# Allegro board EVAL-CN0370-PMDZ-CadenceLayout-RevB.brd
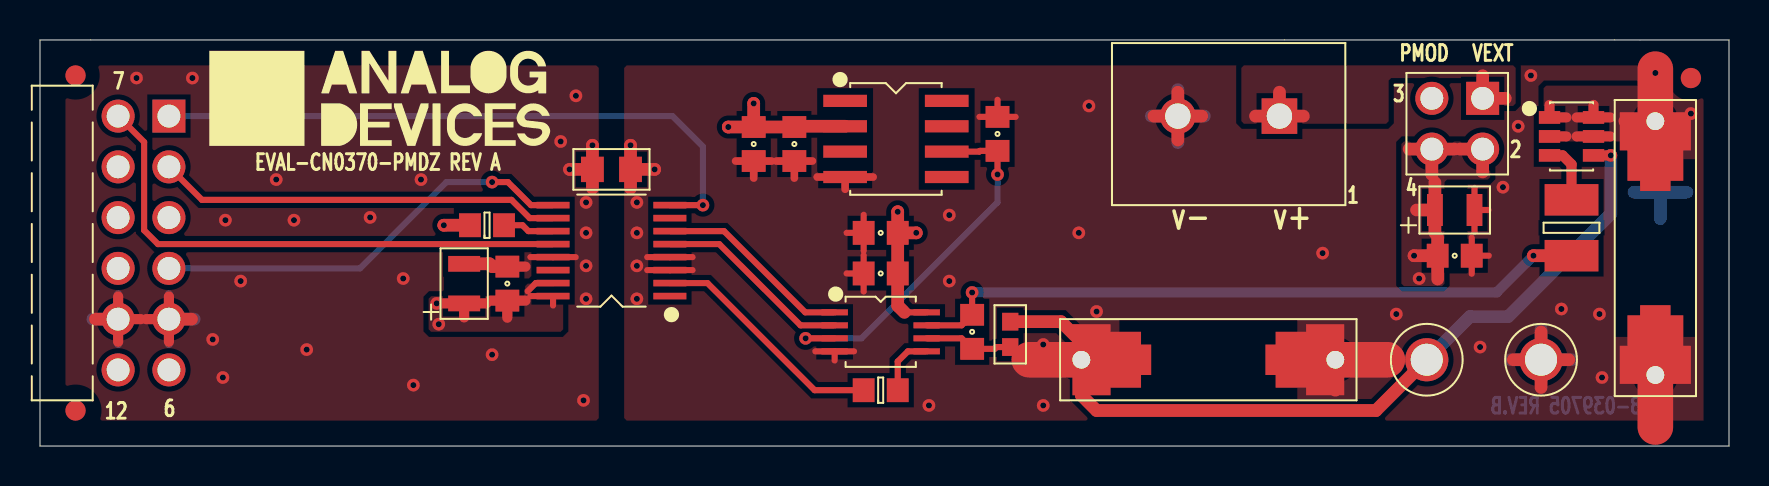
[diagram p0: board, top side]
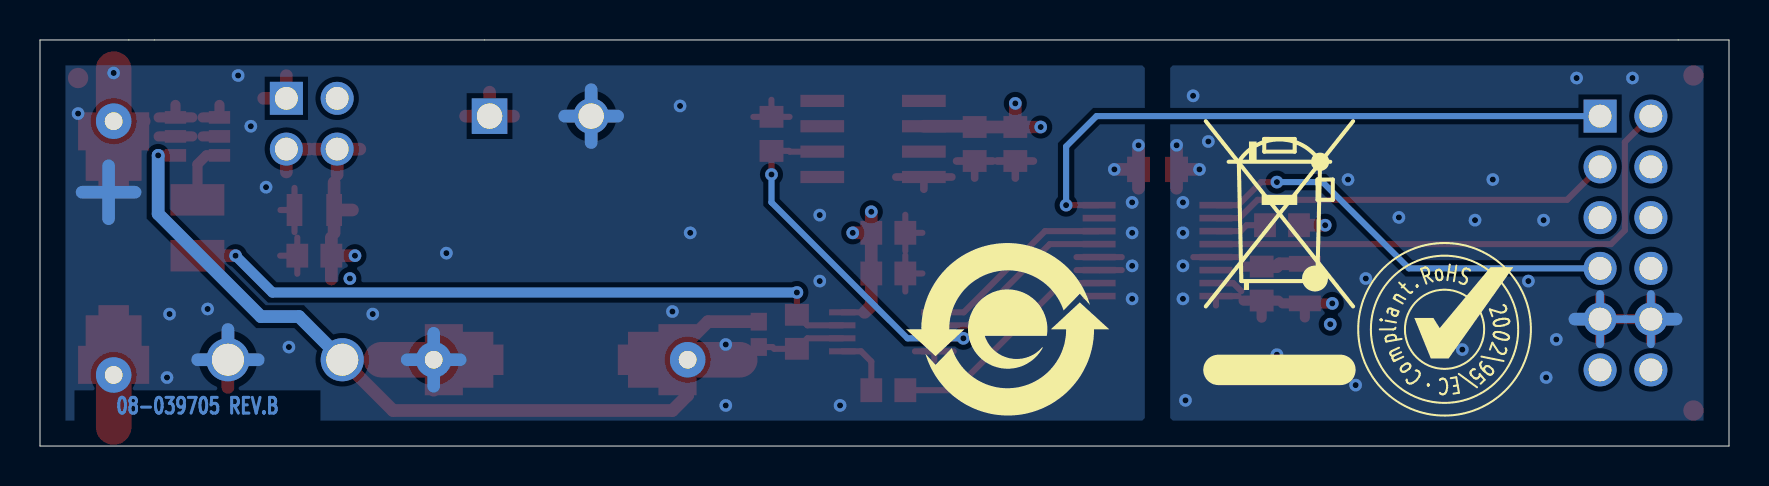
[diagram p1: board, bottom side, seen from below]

Outline 84.45 x 20.32 mm; copper layers: TOP, L2_GND, L3_PWR, BOTTOM. Coordinates in mm from the lower left corner of the outline.
Outline path: 0,20.32 0,0 84.45,0 84.45,20.32 0,20.32

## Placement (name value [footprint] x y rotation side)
A1  ADA4500-2ARMZ  [MSOP8]  42.04 5.71 270 top
AGND  BLK  [CNLOOPTP]  75.06 4.32 0 top
C1  10UF  [C0603]  35.69 15.11 270 top
C2  0.1uF  [C0603]  37.72 15.11 270 top
C4  0.1uF  [C0603]  47.88 15.62 90 top
C5  10UF  [C0603]  42.04 10.67 180 top
C6  0.1uF  [C0603]  42.04 8.64 180 top
C7  10uF  [CPL0805]  21.21 8.13 90 top
C8  0.1uF  [C0603]  23.37 8.13 90 top
C13  22PF  [C0603]  46.61 5.71 270 top
C14  10uF  [CPL0805]  70.74 11.81 0 top
C15  0.1uF  [C0603]  70.74 9.52 0 top
E2  330OHM  [L0805]  28.58 13.84 180 top
LED  TBD_SPACER_500_D37  [R_SPACER_500_D37]  80.77 16.26 270 top
LED_SUPPLY  TSW-102-08-G-D  [CNSAMTEC2X2H338LD36]  72.14 17.4 180 top
NOREF  -  []  1.91 18.41 0 top
NOREF#2  -  [unnamed#2]  82.55 18.41 0 top
NOREF#3  -  []  0 20.32 0 top
NOREF#4  -  []  -149.1 -230.5 0 top
NOREF#5  -  []  1.91 18.41 0 top
NOREF#6  -  []  -157.99 -240.92 0 top
NOREF#7  -  []  84.45 20.32 180 top
NOREF#8  -  []  0 -20.32 0 top
NOREF#9  -  []  0 0 0 top
NOREF#10  -  []  83.51 0 90 top
NOREF#11  -  []  17.02 17.4 0 top
NOREF#12  -  []  -13.97 231.78 0 top
NOREF#13  -  []  0 20.32 0 top
NOREF#14  -  []  0 1.54 0 top
NOREF#15  -  []  84.45 -20.32 90 top
NOREF#16  -  []  0 20.32 270 top
NOREF#17  -  []  84.45 20.32 0 top
NOREF#18  -  []  208.41 236.85 0 top
NOREF#19  -  [unnamed#2]  1.78 1.78 0 top
NOREF#20  -  []  36.83 36.83 0 top
NOREF#21  -  [unnamed#2]  1.78 18.54 0 top
NOREF#22  -  []  -156.72 -239.65 0 top
NOREF#23  -  []  36.07 5.84 180 bottom
NOREF#24  -  []  13.21 19.94 180 bottom
NOREF#25  -  []  14.22 5.84 180 bottom
PMOD  TSW-106-25-F-D-RA  [CNHDRRA2X6H240]  6.45 16.51 270 top
Q1  IRLMS2002TRPBF  [SOT23_6-3]  76.58 15.49 270 top
R1  10K  [R0603]  22.35 11.05 0 top
R2  0  [R0603]  42.04 2.79 0 top
R4  22  [R1210]  76.58 10.92 90 top
R5  6.2K  [R0402]  48.51 5.59 90 top
R_LIMIT  TBD_SPACER_500_D37  [R_SPACER_500_D37]  64.77 4.32 180 top
U1  AD5542ABRUZ  [TSSOP16]  28.58 9.78 90 top
U2  ADR4525BRZ  [SO8]  42.8 15.37 270 top
VEXT  OSTTC022162  [CNHDR1X2H406]  61.98 16.51 180 top
VOUT  BLK  [CNLOOPTP]  69.34 4.32 270 top

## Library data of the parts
A1 = ADA4500_2: User Part Number: UPN; part number: ADA4500_2_SM-ADA4500-2ARMZ,E017613,MSOP8
AGND VOUT = CNTP1P: User Part Number: UPN; alternate symbols: (CNBANANA_ALT); part number: CNTP1P_TH-BLK,E000948,CNLOOPTP
C1 C5 = CAP: Tolerance: 20; User Part Number: UPN; part number: CAP_SM-10UF,6.3V,20,E007143,C0603; tolerance: 20
C2 C4 C6 C8 C15 = CAP: Tolerance: 5; User Part Number: UPN; part number: CAP_SM-0.1UF,16V,5,E022221,C0603; tolerance: 5
C7 C14 = CAPP: Tolerance: 20; User Part Number: UPN; part number: CAPP_SM-10UF,6.3V,20,E020901,CPL0805; tolerance: 20
C13 = CAP: Tolerance: 5; User Part Number: UPN; part number: CAP_SM-22PF,50V,5,E000411,C0603; tolerance: 5
E2 = FERRITE: Tolerance: 25; User Part Number: UPN; alternate symbols: (L1210H59_ALT); part number: FERRITE_SM-330OHM,25,E018120,L0805; tolerance: 25
LED R_LIMIT = RES: User Part Number: UPN; part number: RES_TH-TBD_SPACER_500_D37,E018836,TBD_SPACER_500_D37,TBD_SPACER_500_D37,R_SPACER_500_D37
LED_SUPPLY = CN4P: User Part Number: UPN; part number: CN4P_TH-TSW-102-08-G-D,E006588,CNSAMTEC2X2H338LD36
PMOD = CN12P_V3: User Part Number: UPN; part number: CN12P_V3_TH-TSW-106-25-F-D-RA,E018495,CNHDRRA2X6H240
Q1 = TRANNMOSFET_V17: User Part Number: UPN; part number: TRANNMOSFET_V17_SM-IRLMS2002TRPBF,E018862,SOT23_6-3
R1 = RES: Tolerance: 1; User Part Number: UPN; part number: RES_SM-10K,E003671,1/10W,1,R0603; tolerance: 1
R2 = RES: Tolerance: 5; User Part Number: UPN; part number: RES_SM-0,E006826,1/10W,5,R0603; tolerance: 5
R4 = RES: Tolerance: 5; User Part Number: UPN; part number: RES_SM-22,E013618,1/2W,5,R1210; tolerance: 5
R5 = RES: Tolerance: 5; User Part Number: UPN; part number: RES_SM-6.2K,E003460,1/16W,5,R0402; tolerance: 5
U1 = AD5542A: User Part Number: UPN; part number: AD5542A_SM-AD5542ABRUZ,E016103,TSSOP16
U2 = ADR45XX: User Part Number: UPN; part number: ADR45XX_SM-ADR4525BRZ,E016680,SO8
VEXT = CN2P: User Part Number: UPN; part number: CN2P_TH-OSTTC022162,E016936,CNHDR1X2H406

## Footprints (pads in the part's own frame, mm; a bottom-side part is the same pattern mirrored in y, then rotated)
C0603
  rect 1.092x1.194 smd: 1(-0.851,0) 2(0.851,0)
CNHDR1X2H406
  rect 1.778x1.778 hole 1.27: 1(0,0)
  round 1.778 hole 1.27: 2(5.08,0)
CNHDRRA2X6H240
  rect 1.651x1.651 hole 1.143: 1(0,0)
  round 1.651 hole 1.143: 2(2.54,0) 3(5.08,0) 4(7.62,0) 5(10.16,0) 6(12.7,0) 7(0,-2.54) 8(2.54,-2.54) 9(5.08,-2.54) 10(7.62,-2.54) 11(10.16,-2.54) 12(12.7,-2.54)
CNLOOPTP
  round 2.159 hole 1.6: 1(0,0)
CNSAMTEC2X2H338LD36
  rect 1.651x1.651 hole 1.143: 1(0,0)
  round 1.651 hole 1.143: 2(0,2.54) 3(2.54,0) 4(2.54,2.54)
CPL0805
  rect 0.787x1.6 smd: N(0.991,0) P(-0.991,0)
L0805
  rect 1.143x1.27 smd: 1(-0.953,0) 2(0.953,0)
MSOP8
  rect 0.305x1.321 smd: 1(-0.975,-2.301) 2(-0.325,-2.301) 3(0.325,-2.301) 4(0.975,-2.301) 5(0.975,2.301) 6(0.325,2.301) 7(-0.325,2.301) 8(-0.975,2.301)
R0402
  rect 0.889x0.813 smd: 1(-0.635,0) 2(0.635,0)
R0603
  rect 1.092x1.194 smd: 1(-0.851,0) 2(0.851,0)
R1210
  rect 1.575x2.692 smd: 1(-1.397,0) 2(1.397,0)
R_SPACER_500_D37
  custom 0.889x0.889 hole 0.94: 1(0,0) 2(12.7,0)
SO8
  rect 0.61x2.184 smd: 1(-1.905,-2.54) 2(-0.635,-2.54) 3(0.635,-2.54) 4(1.905,-2.54) 5(1.905,2.54) 6(0.635,2.54) 7(-0.635,2.54) 8(-1.905,2.54)
SOT23_6-3
  rect 0.635x1.067 smd: 1(-0.95,-1.1) 2(0,-1.1) 3(0.95,-1.1) 4(0.95,1.1) 5(0,1.1) 6(-0.95,1.1)
TSSOP16
  rect 0.33x1.651 smd: 1(-2.276,-2.921) 2(-1.626,-2.921) 3(-0.975,-2.921) 4(-0.325,-2.921) 5(0.325,-2.921) 6(0.975,-2.921) 7(1.626,-2.921) 8(2.276,-2.921) 9(2.276,2.921) 10(1.626,2.921) 11(0.975,2.921) 12(0.325,2.921) 13(-0.325,2.921) 14(-0.975,2.921) 15(-1.626,2.921) 16(-2.276,2.921)
unnamed#2
  round 1.016 smd: (0,0)

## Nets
AGND: A1.4(V-) AGND.1(N1) C1.2(N2) C2.2(N2) C4.2(N2) C5.2(N2) C6.2(N2) C14.N(N2) C15.2(N2) E2.1(N1) R_LIMIT.1(N1) U1.3(AGNDF) U1.4(AGNDS) U2.4(GND) VEXT.2(N2)
DGND: C7.N(N2) C8.2(N2) E2.2(N2) PMOD.5(GND1) PMOD.11(GND2) U1.13(DGND)
CS_N: PMOD.1(P1) U1.8(CS_N)
DIN: PMOD.2(P2) U1.10(DIN)
LDAC_N: PMOD.7(P7) U1.12(LDAC_N)
SCLK: PMOD.4(P4) U1.9(SCLK)
UNNAMED_4_AD5542A_I63_CLRN: R1.2(N2) U1.11(CLR_N)
UNNAMED_4_AD5542A_I63_REFF: A1.1(OUT) U1.6(REFF)
UNNAMED_4_AD5542A_I63_REFS: A1.2(INV) U1.5(REFS)
UNNAMED_4_AD5542A_I63_VOUT: R2.1(N1) U1.2(VOUT)
UNNAMED_4_ADA45002_I105_NINV: A1.3(NINV) C4.1(N1) U2.6(VOUT)
UNNAMED_4_ADA45002_I112_INV: A1.6(INV) C13.2(N2) R5.1(N1)
UNNAMED_4_ADA45002_I112_NINV: A1.5(NINV) R2.2(N2)
UNNAMED_4_ADA45002_I112_OUT: A1.7(OUT) C13.1(N1) R4.1(N1)
UNNAMED_4_CAP_I93_N1: C14.P(N1) C15.1(N1) LED.2(N2) LED_SUPPLY.2(N2) LED_SUPPLY.4(N4)
UNNAMED_4_CNTP1P_I108_N1: Q1.4(S) R5.2(N2) R_LIMIT.2(N2) VOUT.1(N1)
UNNAMED_4_RES_I47_N2: Q1.3(G) R4.2(N2)
UNNAMED_4_RES_I110_N1: LED.1(N1) Q1.1(D1) Q1.2(D2) Q1.5(D3) Q1.6(D4)
VEXT: LED_SUPPLY.1(N1) VEXT.1(N1)
VPMOD: A1.8(V+) C1.1(N1) C2.1(N1) C5.1(N1) C6.1(N1) C7.P(N1) C8.1(N1) LED_SUPPLY.3(N3) PMOD.6(VCC1) PMOD.12(VCC2) R1.1(N1) U1.15(VLOGIC) U1.16(VDD) U2.2(VIN)

Pads without a net: PMOD 3 8 9 10; U1 1 7 14; U2 1 3 5 7 8

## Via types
v1: diameter 0.635, hole 0.305, TOP to BOTTOM, 64 vias

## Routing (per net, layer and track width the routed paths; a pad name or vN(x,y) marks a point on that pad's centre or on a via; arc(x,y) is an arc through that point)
AGND: length 84.1
  TOP w0.305: C4.2 48.78,16.47 ; C4.2 46.97,16.47 ; C4.2 47.88,17.33 ; 30.36,8.8 U1.3 32.63,8.8 ; C6.2 41.19,9.54 ; C6.2 41.19,7.73 ; C6.2 40.33,8.64 ; A1.4 40.7,4.74 ; A1.4 38.77,4.74 ; A1.4 39.74,4.28 ; C15.2 71.59,10.43 ; C15.2 71.59,8.62 ; C15.2 72.44,9.52 ; 32.63,9.45 U1.4 30.36,9.45 ; C14.N 71.73,12.92 ; C14.N 72.43,11.81 ; C14.N 71.73,10.7 ; 40.33,10.67 C5.2 ; C5.2 41.19,9.76 ; C5.2 41.19,11.57
  TOP w0.381: C1.2 36.59,14.26 ; C1.2 35.69,13.41 ; C1.2 34.78,14.26 ; C2.2 36.81,14.26 ; C2.2 38.62,14.26 ; C2.2 37.72,13.41 ; U2.4 38.86,13.46 ; U2.4 41.66,13.46 ; U2.4 40.26,12.85
  TOP w0.635: R_LIMIT.1 64.77,2.79 ; R_LIMIT.1 65.97,4.32 ; R_LIMIT.1 64.77,5.71 ; VEXT.2 56.9,15.31 ; VEXT.2 58.09,16.51 ; VEXT.2 55.7,16.51 ; VEXT.2 56.9,17.71 ; E2.1 v1(30.73,13.84) ; E2.1 29.53,12.9 ; E2.1 v1(29.53,15.05) ; AGND.1 75.06,5.7 ; AGND.1 75.06,2.93 ; AGND.1 76.44,4.32 ; AGND.1 73.67,4.32
  L2_GND w0.635: AGND.1 75.06,5.83 ; AGND.1 73.54,4.32 ; AGND.1 75.06,2.8 ; AGND.1 76.57,4.32 ; R_LIMIT.1 64.77,5.64 ; R_LIMIT.1 66.09,4.32 ; R_LIMIT.1 64.77,2.99 ; R_LIMIT.1 63.45,4.32 ; VEXT.2 56.9,17.83 ; VEXT.2 58.22,16.51 ; VEXT.2 55.57,16.51 ; VEXT.2 56.9,15.19
  BOTTOM w0.635: AGND.1 75.06,5.83 ; AGND.1 73.54,4.32 ; AGND.1 76.57,4.32 ; 55.57,16.51 VEXT.2 ; VEXT.2 58.22,16.51 ; VEXT.2 56.9,17.83 ; VEXT.2 56.9,15.19 ; 79.7,12.7 81.03,12.7 ; 81.03,12.7 82.35,12.7 ; 81.03,12.7 81.03,14.02 ; 81.03,12.7 81.03,11.38 ; 64.77,2.99 R_LIMIT.1 ; R_LIMIT.1 64.77,5.64 ; R_LIMIT.1 66.09,4.32 ; R_LIMIT.1 63.45,4.32
  vias: v1(29.85,12.19) v1(29.85,10.67) v1(29.85,9.02) v1(29.85,7.37) v1(44.45,2.03) v1(45.47,11.56) v1(45.47,8.25) v1(50.16,5.08) v1(50.16,2.03) v1(51.94,10.67) v1(52.45,17.02) v1(52.83,6.73) v1(64.13,9.65) v1(67.82,6.6) v1(72.01,4.95) v1(73.15,12.95) v1(73.91,16) v1(74.55,18.54) v1(76.07,6.86) v1(77.98,6.6) v1(78.11,3.43) v1(80.77,18.67) v1(82.55,16.64)
DGND: length 37.9
  TOP w0.305: 24.52,9.45 26.79,9.45
  TOP w0.508: PMOD.11 5.04,6.35 ; PMOD.11 3.91,7.48 ; PMOD.11 3.91,5.22 ; PMOD.5 6.45,7.48 ; PMOD.5 5.31,6.35 ; PMOD.5 6.45,5.22 ; C8.2 24.27,8.98
  TOP w0.635: E2.2 27.62,12.9 ; E2.2 v1(27.62,15.05) ; E2.2 v1(26.48,13.84) ; PMOD.11 2.77,6.35 ; C8.2 22.62,8.98 22.48,9.12 C7.N ; PMOD.5 7.58,6.35
  L2_GND w0.381: PMOD.11 3.91,7.61 ; PMOD.11 3.91,5.09 ; PMOD.11 5.17,6.35 ; 5.19,6.35 PMOD.5 ; PMOD.5 6.45,7.61 ; PMOD.5 6.45,5.09
  L2_GND w0.635: PMOD.5 7.71,6.35 ; PMOD.11 2.65,6.35
  BOTTOM w0.381: PMOD.5 5.19,6.35 ; PMOD.5 6.45,5.09 ; PMOD.5 6.45,7.61 ; PMOD.11 5.17,6.35 ; PMOD.11 3.91,7.61 ; PMOD.11 3.91,5.09
  BOTTOM w0.635: PMOD.11 2.65,6.35 ; PMOD.5 7.71,6.35
  vias: v1(4.83,18.41) v1(7.62,18.41) v1(8.64,5.33) v1(9.14,3.43) v1(9.27,11.3) v1(10.03,8.25) v1(11.81,13.33) v1(12.7,11.3) v1(13.33,4.83) v1(16.51,11.44) v1(18.16,8.38) v1(18.67,3.05) v1(19.05,13.33) v1(22.61,4.57) v1(26.04,15.24) v1(26.8,17.53) v1(27.18,2.29) v1(27.3,12.19) v1(27.3,10.67) v1(27.3,9.02) v1(27.3,7.37)
CS_N: length 31.9
  TOP w0.305: U1.8 v1(33.15,12.05)
  BOTTOM w0.305: v1(33.15,12.05) 33.15,14.99 31.63,16.51 PMOD.1
DIN: length 20.3
  TOP w0.305: 25.65,11.4 24.49,11.4 23.57,12.32 8.1,12.32 PMOD.2
LDAC_N: length 27
  TOP w0.305: 3.91,16.51 5.21,15.21 5.21,10.79 5.9,10.1 25.65,10.1
SCLK: length 21.5
  TOP w0.305: 25.65,12.05 24.55,12.05 23.4,13.21 v1(22.61,13.21)
  BOTTOM w0.305: v1(22.61,13.21) 20.32,13.21 16,8.89 PMOD.4
UNNAMED_4_AD5542A_I63_CLRN: length 2.6
  TOP w0.305: R1.2 24.13,11.05 24.42,10.75 25.65,10.75
UNNAMED_4_AD5542A_I63_REFF: length 9.9
  TOP w0.305: U1.6 34.2,10.75 38.27,6.69 A1.1
UNNAMED_4_AD5542A_I63_REFS: length 9.9
  TOP w0.305: U1.5 33.96,10.1 38.03,6.04 A1.2
UNNAMED_4_AD5542A_I63_VOUT: length 11.9
  TOP w0.305: U1.2 33.38,8.15 38.73,2.79 R2.1
UNNAMED_4_ADA45002_I105_NINV: length 19
  TOP w0.305: U2.6 46.96,14.73 47,14.77 C4.1 v1(47.88,13.59) ; A1.3 v1(38.28,5.39)
  BOTTOM w0.305: v1(38.28,5.39) 41.08,5.39 47.88,12.19 v1(47.88,13.59)
UNNAMED_4_ADA45002_I112_INV: length 4.4
  TOP w0.305: A1.6 46.08,5.39 C13.2 47.74,4.86 47.83,4.95 R5.1
UNNAMED_4_ADA45002_I112_NINV: length 3.1
  TOP w0.305: A1.5 43.4,4.74 42.89,4.23 R2.2
UNNAMED_4_ADA45002_I112_OUT: length 34.3
  TOP w0.305: A1.7 46.08,6.04 C13.1 v1(46.61,7.68)
  TOP w0.635: R4.1 v1(74.68,9.52)
  BOTTOM w0.508: v1(46.61,7.68) 72.83,7.68 v1(74.68,9.52)
UNNAMED_4_CAP_I93_N1: length 16.5
  TOP w0.635: C15.1 69.89,10.43 ; C15.1 69.89,8.36 ; C15.1 v1(68.71,9.52) ; C14.P 69.75,13.18 ; C14.P 68.83,11.81 ; C14.P 69.75,10.67 ; 69.6,14.86 69.6,13.59 ; 69.6,14.86 68.46,14.86 ; 69.6,14.86 70.73,14.86 ; 72.14,13.72 LED_SUPPLY.2 71,14.86
  L3_PWR w0.635: 80.77,3.56 80.77,4.88 ; 80.77,3.56 79.45,3.56 ; 80.77,3.56 82.1,3.56
  vias: v1(68.96,8.38)
UNNAMED_4_CNTP1P_I108_N1: length 41.3
  TOP w0.508: Q1.4 v1(78.55,14.54)
  TOP w0.635: R5.2 51.05,6.22 52.07,5.21 52.07,2.54 52.83,1.78 66.8,1.78 VOUT.1
  BOTTOM w0.635: v1(78.55,14.54) 78.55,11.62 73.41,6.48 71.5,6.48 VOUT.1
UNNAMED_4_RES_I47_N2: length 3.1
  TOP w0.508: R4.2 76.58,14.1 76.13,14.54 Q1.3
UNNAMED_4_RES_I110_N1: length 9.1
  TOP w0.508: 76.32,16.44 Q1.1 75.48,17.07 ; Q1.6 77.68,17.07 ; Q1.6 78.52,16.44 ; Q1.6 76.84,16.44 ; Q1.2 76.32,15.49 ; 76.84,15.49 Q1.5 78.52,15.49
  TOP w0.635: 79.25,16.26 LED.1 80.77,17.53
VEXT: length 5.9
  TOP w0.635: 72.14,18.53 LED_SUPPLY.1 73.27,17.4 ; 63.17,16.51 VEXT.1 ; VEXT.1 61.98,17.71 ; VEXT.1 60.78,16.51
VPMOD: length 39.6
  TOP w0.305: 24.38,7.75 24.79,8.15 25.65,8.15 ; 24.52,7.5 25.65,7.5 25.65,7.03 ; 22.46,7.28 22.53,7.28 ; A1.8 43.22,6.69
  TOP w0.508: C7.P v1(19.84,7.14) ; C7.P 22.32,7.14 ; C7.P 21.21,6.44 ; C8.1 24.27,7.28 ; C8.1 22.53,7.28 ; C8.1 23.37,6.42
  TOP w0.635: C1.1 v1(34.42,15.96) ; C1.1 C2.1 37.76,16 40.26,16 ; C1.1 v1(35.69,17.14) ; 43.22,6.69 42.89,7.02 C6.1 C5.1 ; C5.1 v1(42.89,11.72) ; C5.1 v1(43.81,10.67) ; R1.1 v1(20.19,11.05)
  L3_PWR w0.381: 69.6,16.14 69.6,17.4 70.86,17.4 ; 6.45,5.07 PMOD.6 PMOD.12 3.91,5.07
  L3_PWR w0.635: 6.45,2.55 PMOD.6 7.71,3.81 ; 69.6,18.66 69.6,17.4 68.34,17.4 ; 2.65,3.81 PMOD.12 3.91,2.55
  vias: v1(19.94,6.1)

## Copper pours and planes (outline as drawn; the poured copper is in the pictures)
AGND on TOP: 29.34,1.27 29.21,1.4 29.21,1.4 29.21,18.92 29.34,19.05 81.61,19.05 81.75,17.61 83.18,17.47 83.18,1.27 ; 8 cut-outs
AGND on BOTTOM, L2_GND: 29.34,19.05 83.18,19.05 83.18,1.27 29.34,1.27 29.21,1.4 29.21,1.4 29.21,18.92
DGND on TOP: 2.97,1.27 2.69,2.69 1.27,2.97 1.27,17.45 2.63,17.69 2.87,19.05 27.81,19.05 27.94,18.92 27.94,18.92 27.94,1.4 27.82,1.27 ; 1 cut-out
DGND on BOTTOM, L2_GND: 1.27,1.27 1.27,19.05 27.82,19.05 27.94,18.92 27.94,1.4 27.94,1.4 27.81,1.27
UNNAMED_4_CAP_I93_N1 on TOP: 68.07,8.13 68.2,8 70.1,8 70.23,8.13 70.23,13.21 70.36,13.33 72.39,13.33 72.52,13.46 72.52,15.11 72.39,15.24 68.2,15.24 68.07,15.11
UNNAMED_4_CAP_I93_N1 on L3_PWR: 68.2,9.91 68.2,7.75 68.33,7.62 78.49,7.62 78.74,7.37 78.74,3.3 78.87,3.17 82.3,3.17 82.42,3.3 82.42,9.91 82.3,10.03 68.33,10.03
UNNAMED_4_RES_I110_N1 on TOP: 75.31,18.03 80.9,18.03 81.15,17.78 81.15,15.37 81.03,15.24 75.31,15.24 75.18,15.37 75.18,17.91
VEXT on TOP: 73.79,17.14 73.79,18.92 73.66,19.05 60.2,19.05 60.07,18.92 60.07,16.26 60.2,16.13 67.31,16.13 67.44,16.26 67.44,18.29 67.56,18.41 71.63,18.41 71.75,18.29 71.75,17.14 71.88,17.02 73.66,17.02
VPMOD on TOP: 26.16,8 26.16,5.84 26.04,5.71 19.56,5.71 19.43,5.84 19.43,7.37 19.56,7.49 22.35,7.49 22.61,7.75 24.13,7.75 24.26,7.87 24.26,8 24.38,8.13 26.04,8.13
VPMOD on L3_PWR: 1.27,1.27 1.27,19.05 83.18,19.05 83.18,1.27

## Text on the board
BOTTOM: 08-039705 REV.B
User.Comments: Assy Notes: | 1.E001178 shall be installed to LED | 2.E003504 shall be installed to R_LIMIT | 3.Short Pin 3 and Pin 4 of JP1 by shunt (M022926)
Ref Des/Silkscreen Top: EVAL-CN0370-PMDZ REV A | PMOD | VEXT | v- | v+
PAGE_OUTLINE: R. AMPARO | JUL15 | AUG13 | N/A | B | CHANGED AS PER ECR-055202 | R.AMPARO | NOTES: | 1. THE BOARD SIZE MAY VARY TO COMPENSATE THE COMPONENTS DENSITY OF THE CIRCUIT. | 2. THE BOARD MAY EXTEND TO THE RIGHT AND LOWER PORTION IF THERE IS A NEED TO CHANGE THE BOARD SIZE. | 3. J1 CONNECTOR LOCATION IS FIXED WITH REFERENCE TO THE DISTANCE ON BOARD EDGE ON THE UPPER LEFT PORTION.
DIMENSION: (REF)
DISPLAY_BOTTOM: L2 GND | 08-      -07
User.6: L3 PWR | 08-      -08
User.7: ROHS COMPLIANCE NOTE: | 100 MICRO INCHES NICKEL/ | 3-5 MICRO INCHES GOLD | HOMOGENOUS MATERIALS IN THIS BOARD SHALL BE COMPLIANT | THE EU RoHS DIRECTIVE 2002/95/EC
User.22: FIGURE | SIZE | 12.0 | 37.0 | 45.0 | 50.0 | 63.0 | DRILL CHART: TOP to BOTTOM | ALL UNITS ARE IN MILS | TOLERANCE | +3.0/-3.0 | PLATED | QTY | 64 | 4 | 16 | 2
